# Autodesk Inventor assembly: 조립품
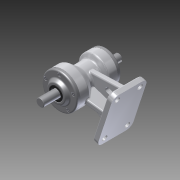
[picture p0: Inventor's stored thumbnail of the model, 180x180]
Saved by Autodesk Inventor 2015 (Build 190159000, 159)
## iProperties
Created: 2015-08
Part Number: 조립품
Document SubType Name: Assembly
Designer: 601
Author: 601
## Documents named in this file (10)
- C:\Users\601\Desktop\450806V1007\조립품.iam
- C:\Users\601\Desktop\450806V1007\축.ipt
- C:\Users\601\Desktop\450806V1007\베어링 6203.ipt
- C:\Users\601\Desktop\450806V1007\베어링 6205.ipt
- C:\Users\601\Desktop\450806V1007\본체.ipt
- C:\Users\601\Desktop\450806V1007\뒤커버.ipt
- C:\Users\601\Desktop\450806V1007\앞커버.ipt
- C:\Users\601\Desktop\450806V1007\오일실 .ipt
- 오일실 .ipt
- C:\Users\601\Desktop\450806V1007\M4x0.5.ipt
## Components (10 placed, 1 different names)
1. M4x0.5:1 — Insert:7
2. M4x0.5:2 — Insert:8
3. M4x0.5:3 — Insert:12
4. M4x0.5:4 — Insert:11
5. M4x0.5:5 — Insert:10
6. M4x0.5:6 — Insert:9
7. M4x0.5:7 — Insert:14
8. M4x0.5:8 — Insert:13
9. M4x0.5:9 — Insert:15
10. M4x0.5:10 — Insert:16
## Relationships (10: Insert 10)
- Insert:7: M4x0.5:1
- Insert:8: M4x0.5:2
- Insert:9: M4x0.5:6
- Insert:10: M4x0.5:5
- Insert:11: M4x0.5:4
- Insert:12: M4x0.5:3
- Insert:13: M4x0.5:8
- Insert:14: M4x0.5:7
- Insert:15: M4x0.5:9
- Insert:16: M4x0.5:10
